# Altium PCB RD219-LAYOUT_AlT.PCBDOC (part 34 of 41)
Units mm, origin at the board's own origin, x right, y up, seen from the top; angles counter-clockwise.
Board outline 209.75 x 159.97 mm, 2 copper layers (TOP, BOTTOM), stack 0 mm thick; 398 components, 199 nets, 1469 pads, 0 vias.
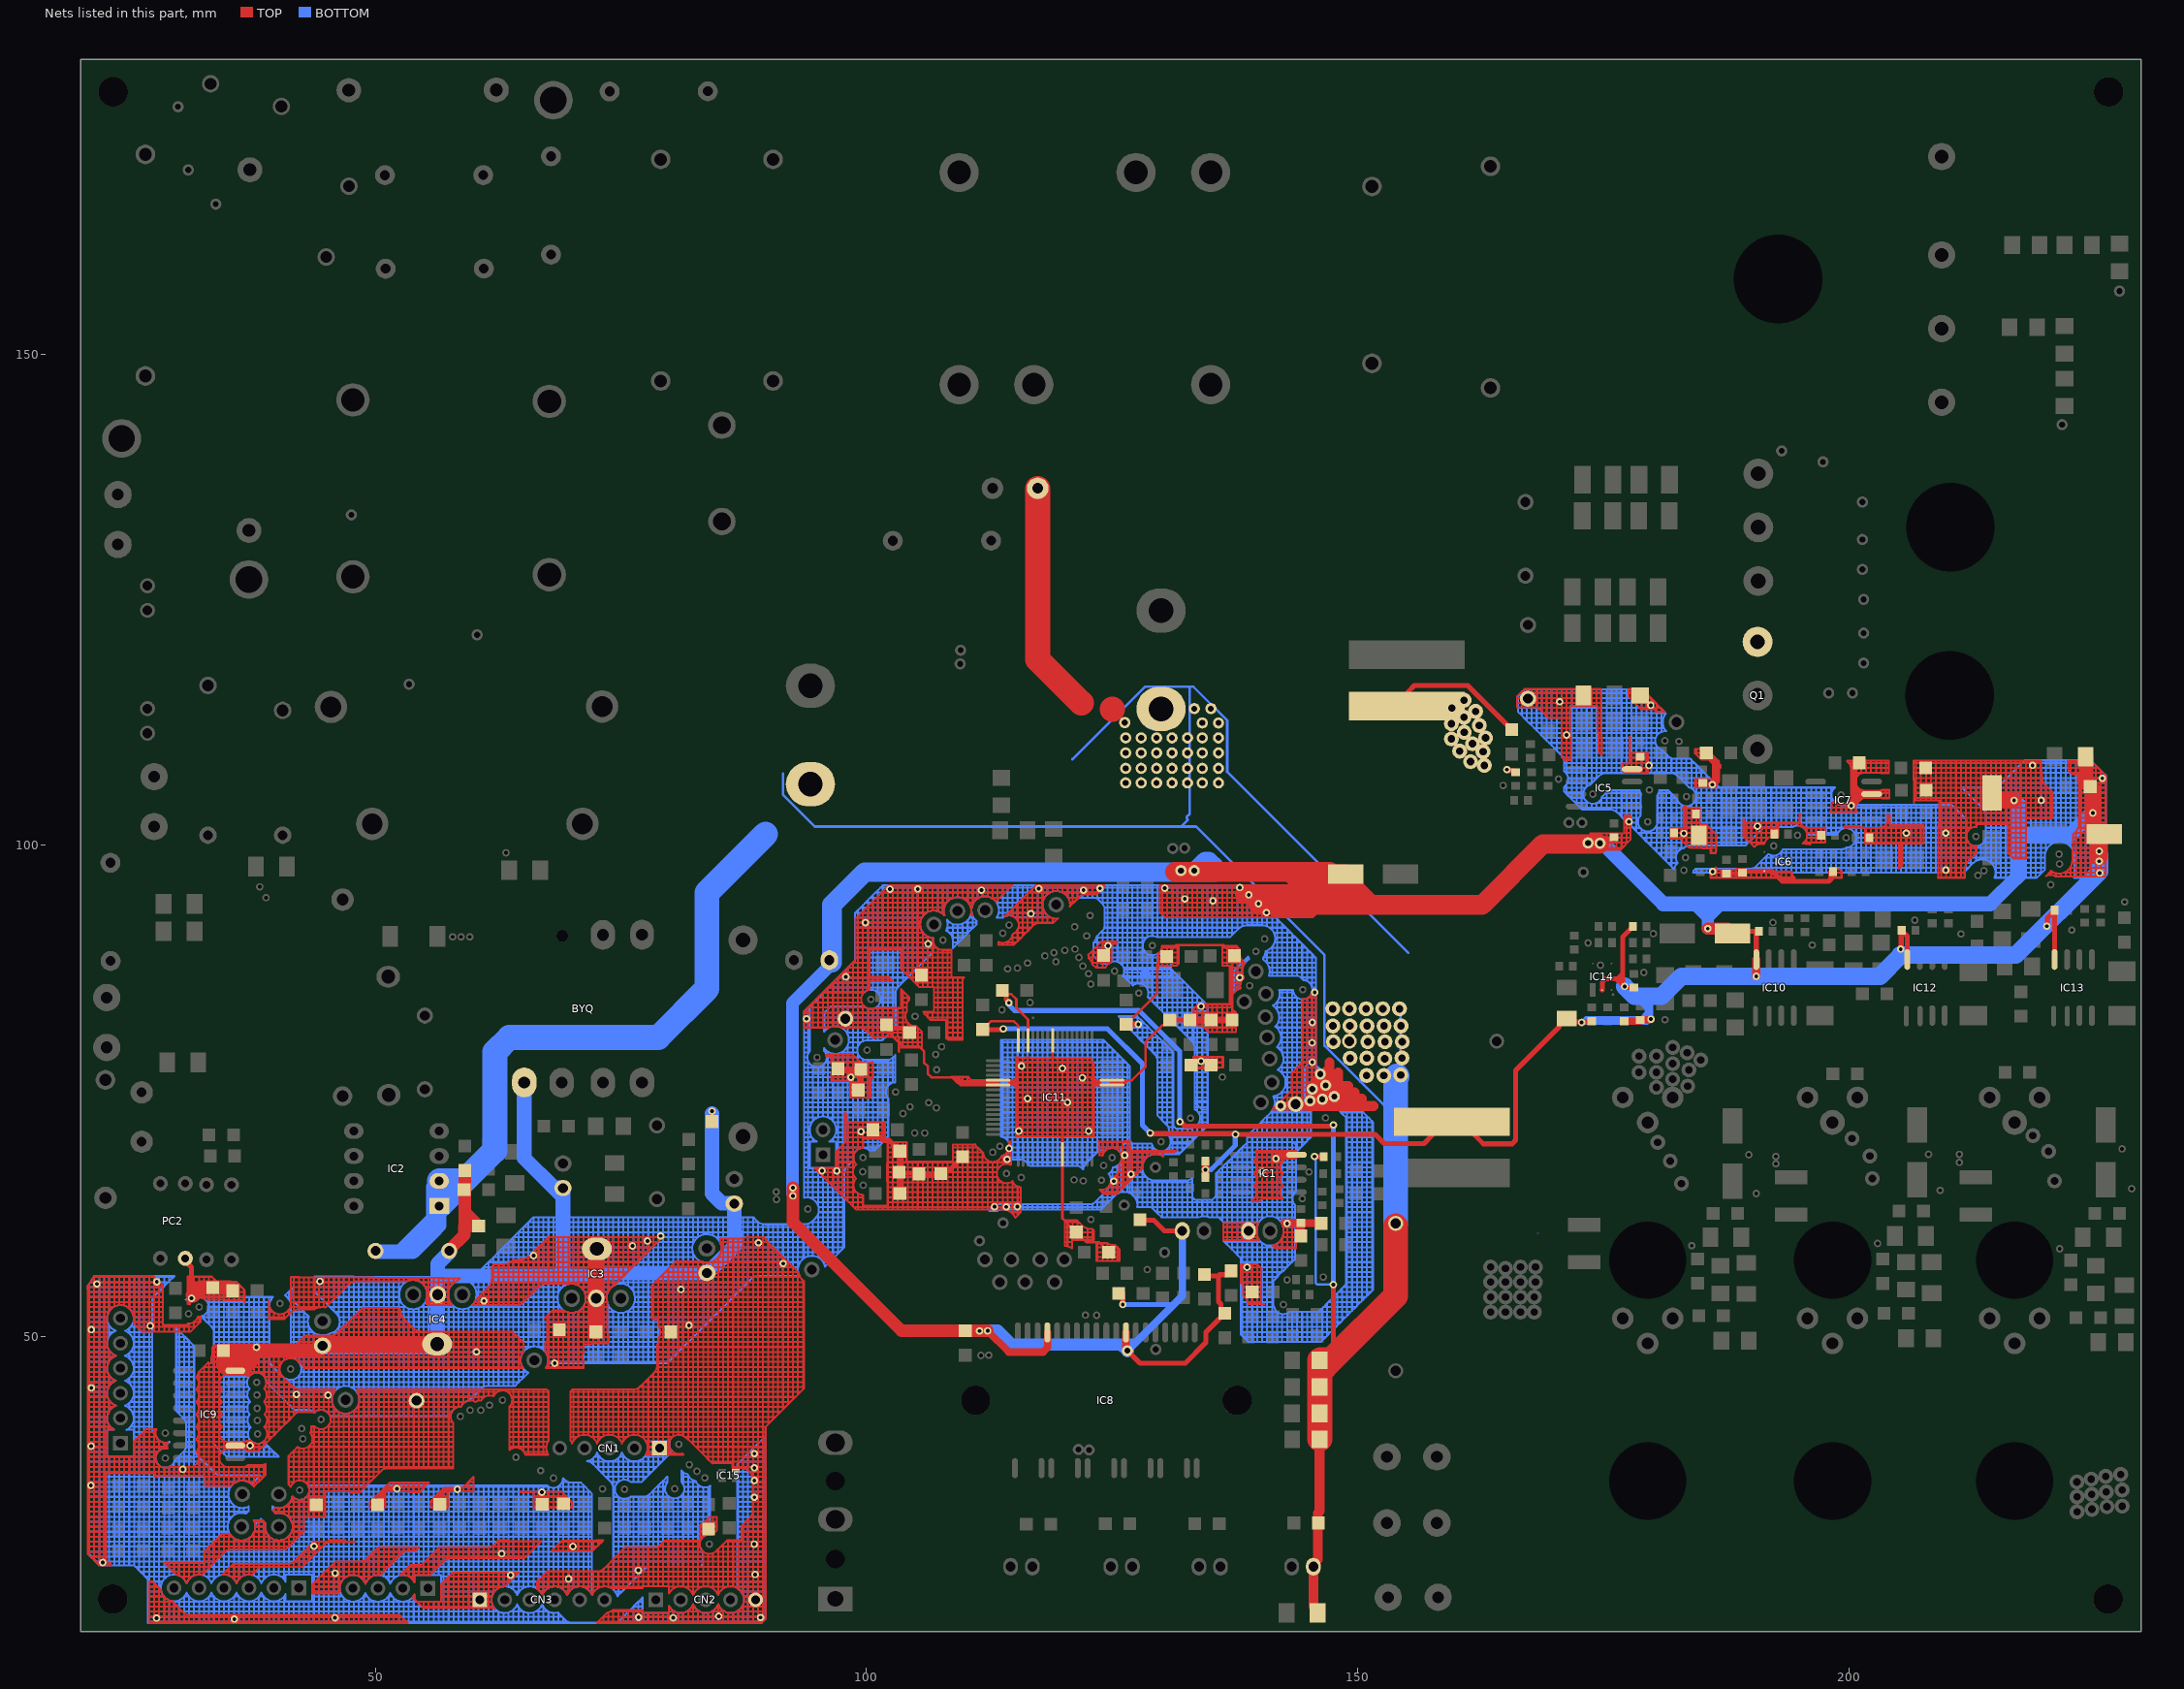
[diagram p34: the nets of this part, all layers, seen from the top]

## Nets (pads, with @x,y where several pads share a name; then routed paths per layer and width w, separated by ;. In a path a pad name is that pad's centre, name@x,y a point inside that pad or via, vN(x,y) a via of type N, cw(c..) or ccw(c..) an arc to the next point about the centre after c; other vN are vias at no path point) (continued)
GND: (continued)
  BOTTOM w0.203: 139.253,63.688 139.761,63.688 ; 139.253,64.196 139.253,64.704 ; 139.253,64.196 139.761,64.196 ; 139.253,64.704 139.253,65.212 ; 139.253,64.704 139.761,64.704 ; 139.253,65.212 139.253,65.72 ; 139.253,65.212 139.761,65.212 ; 139.253,65.72 139.253,66.228 ; 139.253,65.72 139.761,65.72 ; 139.253,66.228 139.253,66.736 ; 139.253,66.228 139.761,66.228 ; 139.253,66.736 139.253,67.244 ; 139.253,66.736 139.761,66.736 ; 139.253,67.244 139.253,67.752 ; 139.253,67.244 139.761,67.244 ; 139.253,67.752 139.253,68.26 ; 139.253,67.752 139.761,67.752 ; 139.253,68.26 139.253,68.768 ; 139.253,68.26 139.761,68.26 ; 139.253,68.768 139.253,69.276 ; 139.253,68.768 139.761,68.768 ; 139.253,69.276 139.253,69.784 ; 139.253,69.276 139.761,69.276 ; 139.253,69.784 139.253,70.292 ; 139.253,69.784 139.761,69.784 ; 139.253,70.292 139.253,70.8 ; 139.253,70.292 139.761,70.292 ; 139.253,70.8 139.253,70.927 ; 139.253,70.8 139.761,70.8 ; 139.253,70.927 139.634,71.308 ; 139.253,91.876 139.761,91.876 ; 139.253,91.876 139.253,92.136 ; 139.253,92.136 139.253,92.644 ; 139.253,92.136 139.761,92.136 ; 139.253,92.644 139.253,93.152 ; 139.253,92.644 139.761,92.644 ; 139.253,93.152 139.761,93.152 ; 139.253,93.152 139.253,93.66 ; 139.253,93.66 139.761,93.66 ; 139.253,93.66 139.253,94.168 ; 139.253,94.168 pad.@139.761,94.168 ; 139.253,94.168 139.253,94.676 ; 139.253,94.676 139.634,94.676 ; 139.253,94.676 pad.@139.253,95.057 ; pad.@139.253,95.057 139.634,94.676 ; 139.634,71.308 139.761,71.308 ; 139.634,71.308 139.761,71.435 ; 139.634,94.676 139.761,94.549 ; 139.72,60.64 139.72,60.917 cw(c141.072,60.917) 139.74,61.148 ; 139.72,60.64 139.72,60.617 ccw(c141.072,60.617) 139.761,60.29 ccw(c141.072,60.617) 139.761,60.288 ; 139.74,61.148 cw(c141.072,60.917) 139.761,61.244 cw(c141.072,60.917) 139.761,61.246 ; 139.761,49.464 140.269,49.464 ; 139.761,49.464 139.761,49.972 ; 139.761,49.972 140.269,49.972 ; 139.761,49.972 139.761,50.48 ; 139.761,50.48 140.269,50.48 ; 139.761,50.48 139.761,50.988 ; 139.761,50.988 140.269,50.988 ; 139.761,50.988 139.761,51.496 ; 139.761,51.496 139.761,52.004 ; 139.761,51.496 140.269,51.496 ; 139.761,52.004 140.269,52.004 ; 139.761,52.004 139.761,52.512 ; 139.761,52.512 139.761,53.02 ; 139.761,52.512 140.269,52.512 ; 139.761,53.02 140.269,53.02 ; 139.761,53.02 139.761,53.528 ; 139.761,53.528 139.761,54.036 ; 139.761,53.528 140.269,53.528 ; 139.761,54.036 139.761,54.544 ; 139.761,54.036 140.269,54.036 ; 139.761,54.544 139.761,55.052 ; 139.761,54.544 140.269,54.544 ; 139.761,55.052 139.761,55.56 ; 139.761,55.052 140.269,55.052 ; 139.761,55.56 139.761,56.068 ; 139.761,55.56 140.269,55.56 ; 139.761,56.068 140.269,56.068 ; 139.761,56.068 139.761,56.576 ; 139.761,56.576 140.269,56.576 ; 139.761,56.576 139.761,57.084 ; 139.761,57.084 139.761,57.592 ; 139.761,57.084 140.269,57.084 ; 139.761,57.592 140.269,57.592 ; 139.761,57.592 139.761,58.1 ; 139.761,58.1 140.269,58.1 ; 139.761,58.1 139.761,58.608 ; 139.761,58.608 139.761,59.116 ; 139.761,58.608 140.269,58.608 ; 139.761,59.116 139.761,59.624 ; 139.761,59.116 140.269,59.116 ; 139.761,59.624 139.761,60.132 ; 139.761,59.624 140.155,59.624 ; 139.761,60.132 139.81,60.132 ; 139.761,60.132 139.761,60.288 ; 139.761,60.288 ccw(c141.072,60.617) 139.81,60.132 ; 139.761,61.246 139.761,61.656 ; 139.761,61.656 139.761,62.164 ; 139.761,62.164 139.761,62.672 ; 139.761,62.164 140.269,62.164 ; 139.761,62.672 139.761,63.18 ; 139.761,62.672 140.269,62.672 ; 139.761,63.18 139.761,63.688 ; 139.761,63.18 140.269,63.18 ; 139.761,63.688 139.761,64.196 ; 139.761,63.688 140.269,63.688 ; 139.761,64.196 139.761,64.704 ; 139.761,64.196 140.269,64.196 ; 139.761,64.704 139.761,65.212 ; 139.761,64.704 140.269,64.704 ; 139.761,65.212 139.761,65.72 ; 139.761,65.212 140.269,65.212 ; 139.761,65.72 139.761,66.228 ; 139.761,65.72 140.269,65.72 ; 139.761,66.228 139.761,66.736 ; 139.761,66.228 140.269,66.228 ; 139.761,66.736 139.761,67.244 ; 139.761,66.736 pad.@140.269,66.736 ; 139.761,67.244 139.761,67.752 ; 139.761,67.244 140.269,67.244 ; 139.761,67.752 139.761,68.26 ; 139.761,67.752 140.269,67.752 ; 139.761,68.26 139.761,68.768 ; 139.761,68.26 140.269,68.26 ; 139.761,68.768 139.761,69.276 ; 139.761,68.768 140.269,68.768 ; 139.761,69.276 139.761,69.784 ; 139.761,69.276 140.269,69.276 ; 139.761,69.784 139.761,70.292 ; 139.761,69.784 140.269,69.784 ; 139.761,70.292 139.761,70.8 ; 139.761,70.292 140.269,70.292 ; 139.761,70.8 139.761,71.308 ; 139.761,70.8 140.269,70.8 ; 139.761,71.308 140.269,71.308 ; 139.761,71.308 139.761,71.435 ; 139.761,71.435 140.142,71.816 ; 139.761,91.876 139.761,92.136 ; 139.761,91.876 140.242,91.876 cw(c140.242,90.524) 140.269,91.875 ; 139.761,92.136 139.761,92.644 ; 139.761,92.136 140.269,92.136 ; 139.761,92.644 139.761,93.152 ; 139.761,92.644 140.269,92.644 ; 139.761,93.152 140.269,93.152 ; 139.761,93.152 139.761,93.66 ; 139.761,93.66 pad.@139.761,94.168 ; 139.761,93.66 140.269,93.66 ; pad.@139.761,94.168 139.761,94.549 ; pad.@139.761,94.168 pad.@140.142,94.168 ; 139.761,94.549 pad.@140.142,94.168 ; 139.81,60.132 ccw(c141.072,60.617) 140.155,59.624 ; 140.142,71.816 140.269,71.816 ; 140.142,71.816 140.269,71.943 ; pad.@140.142,94.168 pad.@140.269,94.041 ; 140.269,49.464 140.269,49.972 ; 140.269,49.464 140.777,49.464 ; 140.269,49.972 140.269,50.48 ; 140.269,49.972 140.777,49.972 ; 140.269,50.48 140.269,50.988 ; 140.269,50.48 140.777,50.48 ; 140.269,50.988 140.269,51.496 ; 140.269,50.988 140.777,50.988 ; 140.269,51.496 140.269,52.004 ; 140.269,51.496 140.777,51.496 ; 140.269,52.004 140.777,52.004 ; 140.269,52.004 140.269,52.512 ; 140.269,52.512 140.269,53.02 ; 140.269,52.512 140.777,52.512 ; 140.269,53.02 140.777,53.02 ; 140.269,53.02 140.269,53.528 ; 140.269,53.528 140.269,54.036 ; 140.269,53.528 140.777,53.528 ; 140.269,54.036 140.269,54.544 ; 140.269,54.036 140.777,54.036 ; 140.269,54.544 140.269,55.052 ; 140.269,54.544 140.777,54.544 ; 140.269,55.052 140.269,55.56 ; 140.269,55.052 140.777,55.052 ; 140.269,55.56 140.269,56.068 ; 140.269,55.56 140.777,55.56 ; 140.269,56.068 140.269,56.576 ; 140.269,56.068 140.777,56.068 ; 140.269,56.576 140.269,57.084 ; 140.269,56.576 140.777,56.576 ; 140.269,57.084 140.269,57.592 ; 140.269,57.084 140.777,57.084 ; 140.269,57.592 140.777,57.592 ; 140.269,57.592 140.269,58.1 ; 140.269,58.1 140.777,58.1 ; 140.269,58.1 140.269,58.608 ; 140.269,58.608 140.269,59.116 ; 140.269,58.608 140.777,58.608 ; 140.269,59.116 140.777,59.116 ; 140.269,62.004 cw(c141.072,60.917) 140.544,62.161 cw(c141.072,60.917) 140.551,62.164 ; 140.269,62.004 140.269,62.164 ; 140.269,62.164 140.269,62.672 ; 140.269,62.164 140.551,62.164 ; 140.269,62.672 140.269,63.18 ; 140.269,62.672 140.777,62.672 ; 140.269,63.18 140.269,63.688 ; 140.269,63.18 140.777,63.18 ; 140.269,63.688 140.269,64.196 ; 140.269,63.688 140.777,63.688 ; 140.269,64.196 140.269,64.704 ; 140.269,64.196 140.777,64.196 ; 140.269,64.704 140.269,65.212 ; 140.269,64.704 140.777,64.704 ; 140.269,65.212 140.269,65.72 ; 140.269,65.212 140.777,65.212 ; 140.269,65.72 140.269,66.228 ; 140.269,65.72 140.777,65.72 ; 140.269,66.228 pad.@140.269,66.736 ; 140.269,66.228 140.777,66.228 ; pad.@140.269,66.736 140.777,66.736 ; pad.@140.269,66.736 140.269,67.244 ; 140.269,67.244 140.269,67.752 ; 140.269,67.244 140.777,67.244 ; 140.269,67.752 140.269,68.26 ; 140.269,67.752 140.777,67.752 ; 140.269,68.26 140.269,68.768 ; 140.269,68.26 140.777,68.26 ; 140.269,68.768 140.269,69.276 ; 140.269,68.768 140.777,68.768 ; 140.269,69.276 140.269,69.784 ; 140.269,69.276 140.777,69.276 ; 140.269,69.784 140.269,70.292 ; 140.269,69.784 140.777,69.784 ; 140.269,70.292 140.269,70.8 ; 140.269,70.292 140.777,70.292 ; 140.269,70.8 140.269,71.308 ; 140.269,70.8 140.777,70.8 ; 140.269,71.308 140.269,71.816 ; 140.269,71.308 140.777,71.308 ; 140.269,71.816 140.777,71.816 ; 140.269,71.816 140.269,71.943 ; 140.269,71.943 140.65,72.324 ; 140.269,91.875 cw(c140.242,90.524) 140.777,91.765 ; 140.269,91.875 140.269,92.136 ; 140.269,92.136 140.269,92.644 ; 140.269,92.136 140.777,92.136 ; 140.269,92.644 140.269,93.152 ; 140.269,92.644 140.777,92.644 ; 140.269,93.152 pad.@140.777,93.152 ; 140.269,93.152 140.269,93.66 ; 140.269,93.66 140.65,93.66 ; 140.269,93.66 pad.@140.269,94.041 ; pad.@140.269,94.041 140.65,93.66 ; 140.363,88.38 cw(c139.634,87.183) 140.718,88.072 ; 140.384,88.58 ccw(c139.634,89.215) 140.608,89.088 ; 140.384,88.58 140.777,88.58 ; 140.551,62.164 cw(c141.072,60.917) 140.768,62.234 cw(c141.072,60.917) 140.777,62.236 ; 140.608,89.088 140.777,89.088 ; 140.65,72.324 140.777,72.324 ; 140.65,72.324 140.777,72.451 ; 140.65,93.66 140.777,93.533 ; 140.718,88.072 cw(c139.634,87.183) 140.777,87.994 ; 140.718,88.072 140.777,88.072 ; 140.777,49.464 140.777,49.972 ; 140.777,49.464 141.285,49.464 ; 140.777,49.972 140.777,50.48 ; 140.777,49.972 141.285,49.972 ; 140.777,50.48 140.777,50.988 ; 140.777,50.48 141.285,50.48 ; 140.777,50.988 140.777,51.496 ; 140.777,50.988 141.285,50.988 ; 140.777,51.496 140.777,52.004 ; 140.777,51.496 141.285,51.496 ; 140.777,52.004 140.777,52.512 ; 140.777,52.004 141.285,52.004 ; 140.777,52.512 140.777,53.02 ; 140.777,52.512 141.285,52.512 ; 140.777,53.02 140.777,53.528 ; 140.777,53.02 141.285,53.02 ; 140.777,53.528 140.777,54.036 ; 140.777,53.528 141.285,53.528 ; 140.777,54.036 140.777,54.544 ; 140.777,54.036 141.285,54.036 ; 140.777,54.544 140.777,55.052 ; 140.777,54.544 141.285,54.544 ; 140.777,55.052 140.777,55.56 ; 140.777,55.052 141.285,55.052 ; 140.777,55.56 140.777,56.068 ; 140.777,55.56 141.285,55.56 ; 140.777,56.068 140.777,56.576 ; 140.777,56.068 141.285,56.068 ; 140.777,56.576 140.777,57.084 ; 140.777,56.576 141.285,56.576 ; 140.777,57.084 140.777,57.592 ; 140.777,57.084 141.285,57.084 ; 140.777,57.592 140.777,58.1 ; 140.777,57.592 141.285,57.592 ; 140.777,58.1 140.777,58.608 ; 140.777,58.1 141.285,58.1 ; 140.777,58.608 140.777,59.116 ; 140.777,58.608 141.285,58.608 ; 140.777,59.116 141.285,59.116 ; 140.777,59.116 140.777,59.298 ; 140.777,59.298 ccw(c141.072,60.617) 141.072,59.265 ccw(c141.072,60.617) 141.283,59.282 ccw(c141.072,60.617) 141.285,59.282 ; 140.777,62.236 cw(c141.072,60.917) 141.283,62.252 cw(c141.072,60.917) 141.285,62.252 ; 140.777,62.236 140.777,62.672 ; 140.777,62.672 140.777,63.18 ; 140.777,62.672 141.285,62.672 ; 140.777,63.18 140.777,63.688 ; 140.777,63.18 141.285,63.18 ; 140.777,63.688 140.777,64.196 ; 140.777,63.688 141.285,63.688 ; 140.777,64.196 140.777,64.704 ; 140.777,64.196 141.285,64.196 ; 140.777,64.704 140.777,65.212 ; 140.777,64.704 141.285,64.704 ; 140.777,65.212 140.777,65.72 ; 140.777,65.212 141.285,65.212 ; 140.777,65.72 140.777,66.228 ; 140.777,65.72 141.285,65.72 ; 140.777,66.228 140.777,66.736 ; 140.777,66.228 141.285,66.228 ; 140.777,66.736 140.777,67.244 ; 140.777,66.736 141.285,66.736 ; 140.777,67.244 140.777,67.752 ; 140.777,67.244 141.285,67.244 ; 140.777,67.752 140.777,68.26 ; 140.777,67.752 141.285,67.752 ; 140.777,68.26 140.777,68.768 ; 140.777,68.26 141.285,68.26 ; 140.777,68.768 141.285,68.768 ; 140.777,68.768 140.777,69.276 ; 140.777,69.276 141.285,69.276 ; 140.777,69.276 140.777,69.784 ; 140.777,69.784 140.777,70.292 ; 140.777,69.784 141.285,69.784 ; 140.777,70.292 141.285,70.292 ; 140.777,70.292 140.777,70.8 ; 140.777,70.8 140.777,71.308 ; 140.777,70.8 141.285,70.8 ; 140.777,71.308 140.777,71.816 ; 140.777,71.308 141.285,71.308 ; 140.777,71.816 140.777,72.324 ; 140.777,71.816 141.285,71.816 ; 140.777,72.324 141.285,72.324 ; 140.777,72.324 140.777,72.451 ; 140.777,72.451 141.158,72.832 ; 140.777,87.994 cw(c139.634,87.183) 140.981,87.569 cw(c139.634,87.183) 140.983,87.564 ; 140.777,87.994 140.777,88.072 ; 140.777,88.072 140.777,88.58 ; 140.777,88.072 141.285,88.072 ; 140.777,88.58 141.285,88.58 ; 140.777,88.58 140.777,89.088 ; 140.777,89.088 141.285,89.088 ; 140.777,89.088 140.777,89.283 ; 140.777,89.283 ccw(c140.242,90.524) 141.225,89.596 ; 140.777,91.765 cw(c140.242,90.524) 141.017,91.631 cw(c140.242,90.524) 141.022,91.628 ; 140.777,91.765 140.777,92.136 ; 140.777,92.136 140.777,92.644 ; 140.777,92.136 141.285,92.136 ; 140.777,92.644 pad.@140.777,93.152 ; 140.777,92.644 141.285,92.644 ; pad.@140.777,93.152 141.158,93.152 ; pad.@140.777,93.152 140.777,93.533 ; 140.777,93.533 141.158,93.152 ; 140.961,86.731 ccw(c139.634,87.183) 141.03,87.056 ; 140.961,86.731 141.285,86.731 ; 140.983,87.564 cw(c139.634,87.183) 141.03,87.061 cw(c139.634,87.183) 141.03,87.056 ; 140.983,87.564 141.285,87.564 ; 141.022,91.628 cw(c140.242,90.524) 141.285,91.384 ; 141.022,91.628 141.285,91.628 ; 141.03,87.056 141.285,87.056 ; 141.158,72.832 141.285,72.832 ; 141.158,72.832 141.285,72.959 ; 141.158,93.152 141.285,93.025 ; 141.225,89.596 ccw(c140.242,90.524) 141.278,89.655 ccw(c140.242,90.524) 141.285,89.664 ; 141.225,89.596 141.285,89.596 ; 141.285,49.464 141.285,49.972 ; 141.285,49.464 141.793,49.464 ; 141.285,49.972 141.285,50.48 ; 141.285,49.972 141.793,49.972 ; 141.285,50.48 141.285,50.988 ; 141.285,50.48 141.793,50.48 ; 141.285,50.988 141.285,51.496 ; 141.285,50.988 141.793,50.988 ; 141.285,51.496 141.285,52.004 ; 141.285,51.496 141.793,51.496 ; 141.285,52.004 141.285,52.512 ; 141.285,52.004 141.793,52.004 ; 141.285,52.512 141.793,52.512 ; 141.285,52.512 141.285,53.02 ; 141.285,53.02 141.285,53.528 ; 141.285,53.02 141.479,53.02 ; 141.285,53.528 141.285,54.036 ; 141.285,53.528 141.412,53.528 ; 141.285,54.036 141.285,54.544 ; 141.285,54.036 141.412,54.036 ; 141.285,54.544 141.285,55.052 ; 141.285,54.544 141.412,54.544 ; 141.285,55.052 141.285,55.56 ; 141.285,55.052 141.412,55.052 ; 141.285,55.56 141.285,56.068 ; 141.285,55.56 141.412,55.56 ; 141.285,56.068 141.793,56.068 ; 141.285,56.068 141.285,56.576 ; 141.285,56.576 141.793,56.576 ; 141.285,56.576 141.285,57.084 ; 141.285,57.084 141.285,57.592 ; 141.285,57.084 141.793,57.084 ; 141.285,57.592 141.793,57.592 ; 141.285,57.592 141.285,58.1 ; 141.285,58.1 141.793,58.1 ; 141.285,58.1 141.285,58.608 ; 141.285,58.608 141.285,59.116 ; 141.285,58.608 141.793,58.608 ; 141.285,59.116 141.793,59.116 ; 141.285,59.116 141.285,59.282 ; 141.285,59.282 ccw(c141.072,60.617) 141.788,59.471 ccw(c141.072,60.617) 141.793,59.474 ; 141.285,62.252 cw(c141.072,60.917) 141.593,62.164 ; 141.285,62.252 141.285,62.672 ; 141.285,62.672 141.285,63.18 ; 141.285,62.672 141.793,62.672 ; 141.285,63.18 141.285,63.688 ; 141.285,63.18 141.793,63.18 ; 141.285,63.688 141.285,64.196 ; 141.285,63.688 141.793,63.688 ; 141.285,64.196 141.285,64.704 ; 141.285,64.196 141.793,64.196 ; 141.285,64.704 141.285,65.212 ; 141.285,64.704 141.793,64.704 ; 141.285,65.212 141.285,65.72 ; 141.285,65.212 141.793,65.212 ; 141.285,65.72 141.285,66.228 ; 141.285,65.72 141.793,65.72 ; 141.285,66.228 141.285,66.736 ; 141.285,66.228 141.793,66.228 ; 141.285,66.736 141.285,67.244 ; 141.285,66.736 141.793,66.736 ; 141.285,67.244 141.285,67.752 ; 141.285,67.244 141.793,67.244 ; 141.285,67.752 141.793,67.752 ; 141.285,67.752 141.285,68.26 ; 141.285,68.26 141.285,68.768 ; 141.285,68.26 pad.@141.793,68.26 ; 141.285,68.768 141.285,69.276 ; 141.285,68.768 141.793,68.768 ; 141.285,69.276 141.285,69.784 ; 141.285,69.276 141.793,69.276 ; 141.285,69.784 141.285,70.292 ; 141.285,69.784 141.793,69.784 ; 141.285,70.292 141.793,70.292 ; 141.285,70.292 141.285,70.8 ; 141.285,70.8 141.285,71.308 ; 141.285,70.8 141.793,70.8 ; 141.285,71.308 141.285,71.816 ; 141.285,71.308 141.793,71.308 ; 141.285,71.816 141.285,72.324 ; 141.285,71.816 141.793,71.816 ; 141.285,72.324 141.285,72.832 ; 141.285,72.324 141.793,72.324 ; 141.285,72.832 141.793,72.832 ; 141.285,72.832 141.285,72.959 ; 141.285,72.959 141.412,73.086 ; 141.285,86.731 141.285,87.056 ; 141.285,86.731 141.793,86.731 ; 141.285,87.056 141.285,87.564 ; 141.285,87.056 141.793,87.056 ; 141.285,87.564 141.285,88.072 ; 141.285,87.564 141.793,87.564 ; 141.285,88.072 141.285,88.58 ; 141.285,88.072 141.793,88.072 ; 141.285,88.58 141.285,89.088 ; 141.285,88.58 141.793,88.58 ; 141.285,89.088 141.285,89.596 ; 141.285,89.088 141.793,89.088 ; 141.285,89.596 141.793,89.596 ; 141.285,89.596 141.285,89.664 ; 141.285,89.664 ccw(c140.242,90.524) 141.527,90.104 ; 141.285,91.384 cw(c140.242,90.524) 141.455,91.12 ; 141.285,91.384 141.285,91.628 ; 141.285,91.628 141.285,92.136 ; 141.285,91.628 141.793,91.628 ; 141.285,92.136 141.285,92.644 ; 141.285,92.136 141.793,92.136 ; 141.285,92.644 141.285,93.025 ; 141.285,92.644 141.666,92.644 ; 141.285,93.025 141.666,92.644 ; 141.318,73.086 ccw(c140.142,73.848) 141.448,73.34 ; 141.318,73.086 141.412,73.086 ; 141.412,53.528 141.412,54.036 ; 141.412,54.036 141.412,54.544 ; 141.412,54.544 141.412,55.052 ; 141.412,55.052 141.412,55.56 ; 141.412,55.56 141.412,55.687 141.793,56.068 ; 141.412,73.086 pad.@141.793,73.086 ; 141.412,73.086 pad.@141.666,73.34 ; 141.448,73.34 ccw(c140.142,73.848) 141.544,73.848 ; 141.448,73.34 pad.@141.666,73.34 ; 141.448,74.356 cw(c140.142,73.848) 141.544,73.848 ; 141.448,74.356 141.793,74.356 ; 141.455,91.12 cw(c140.242,90.524) 141.457,91.117 cw(c140.242,90.524) 141.591,90.612 ; 141.455,91.12 141.793,91.12 ; 141.479,53.02 ccw(c142.428,53.274) 141.793,52.524 ; 141.527,90.104 ccw(c140.242,90.524) 141.594,90.524 ccw(c140.242,90.524) 141.591,90.612 ; 141.527,90.104 141.793,90.104 ; 141.544,73.848 pad.@141.793,73.848 ; 141.591,90.612 141.793,90.612 ; 141.593,62.164 cw(c141.072,60.917) 141.788,62.063 cw(c141.072,60.917) 141.793,62.06 ; 141.593,62.164 141.793,62.164 ; 141.599,83.5 cw(c140.598,82.519) 141.787,83.262 cw(c140.598,82.519) 141.793,83.251 ; 141.599,83.5 141.793,83.5 ; pad.@141.666,73.34 pad.@141.793,73.34 ; pad.@141.666,73.34 pad.@141.793,73.467 ; 141.666,92.644 141.793,92.517 ; 141.734,84.008 ccw(c140.65,84.897) 141.793,84.086 ; 141.734,84.008 141.793,84.008 ; 141.743,81.468 cw(c140.777,80.452) 141.793,81.418 ; 141.743,81.468 141.793,81.468 ; 141.793,49.464 141.793,49.972 ; 141.793,49.464 142.301,49.464 ; 141.793,49.972 141.793,50.48 ; 141.793,49.972 142.301,49.972 ; 141.793,50.48 141.793,50.988 ; 141.793,50.48 142.301,50.48 ; 141.793,50.988 141.793,51.496 ; 141.793,50.988 142.301,50.988 ; 141.793,51.496 141.793,52.004 ; 141.793,51.496 142.301,51.496 ; 141.793,52.004 141.793,52.512 ; 141.793,52.004 142.301,52.004 ; 141.793,52.512 141.793,52.524 ; 141.793,52.512 141.808,52.512 ; 141.793,52.524 ccw(c142.428,53.274) 141.808,52.512 ; 141.793,56.068 141.793,56.576 ; 141.793,56.068 141.901,56.175 ; 141.793,56.576 141.793,57.084 ; 141.793,56.576 142.223,56.576 ; 141.793,57.084 141.793,57.592 ; 141.793,57.084 142.301,57.084 ; 141.793,57.592 142.301,57.592 ; 141.793,57.592 141.793,58.1 ; 141.793,58.1 142.301,58.1 ; 141.793,58.1 141.793,58.608 ; 141.793,58.608 141.793,59.116 ; 141.793,58.608 142.301,58.608 ; 141.793,59.116 142.301,59.116 ; 141.793,59.116 141.793,59.474 ; 141.793,62.06 cw(c141.072,60.917) 142.204,61.656 ; 141.793,62.06 141.793,62.164 ; 141.793,62.164 141.793,62.672 ; 141.793,62.164 142.301,62.164 ; 141.793,62.672 141.793,63.18 ; 141.793,62.672 142.301,62.672 ; 141.793,63.18 141.793,63.688 ; 141.793,63.18 142.301,63.18 ; 141.793,63.688 141.793,64.196 ; 141.793,63.688 142.301,63.688 ; 141.793,64.196 141.793,64.704 ; 141.793,64.196 142.301,64.196 ; 141.793,64.704 141.793,65.212 ; 141.793,64.704 142.301,64.704 ; 141.793,65.212 141.793,65.72 ; 141.793,65.212 142.301,65.212 ; 141.793,65.72 141.793,66.228 ; 141.793,65.72 142.301,65.72 ; 141.793,66.228 141.793,66.736 ; 141.793,66.228 142.301,66.228 ; 141.793,66.736 141.793,67.244 ; 141.793,66.736 142.301,66.736 ; 141.793,67.244 141.793,67.752 ; 141.793,67.244 142.301,67.244 ; 141.793,67.752 142.301,67.752 ; 141.793,67.752 pad.@141.793,68.26 ; pad.@141.793,68.26 141.793,68.768 ; pad.@141.793,68.26 142.301,68.26 ; 141.793,68.768 141.793,69.276 ; 141.793,68.768 142.301,68.768 ; 141.793,69.276 141.793,69.784 ; 141.793,69.276 142.301,69.276 ; 141.793,69.784 141.793,70.292 ; 141.793,69.784 142.301,69.784 ; 141.793,70.292 142.301,70.292 ; 141.793,70.292 141.793,70.8 ; 141.793,70.8 141.793,71.308 ; 141.793,70.8 142.301,70.8 ; 141.793,71.308 141.793,71.816 ; 141.793,71.308 142.301,71.308 ; 141.793,71.816 141.793,72.324 ; 141.793,71.816 142.301,71.816 ; 141.793,72.324 141.793,72.832 ; 141.793,72.324 142.301,72.324 ; 141.793,72.832 pad.@141.793,73.086 ; 141.793,72.832 142.301,72.832 ; pad.@141.793,73.086 pad.@141.793,73.34 ; pad.@141.793,73.086 pad.@142.301,73.086 ; pad.@141.793,73.34 pad.@141.793,73.467 ; pad.@141.793,73.34 pad.@142.301,73.34 ; pad.@141.793,73.467 pad.@141.793,73.848 ; pad.@141.793,73.467 142.047,73.721 pad.@142.301,73.721 ; pad.@141.793,73.848 141.793,74.356 ; pad.@141.793,73.848 pad.@142.301,73.848 ; 141.793,74.356 142.301,74.356 ; 141.793,74.356 141.793,74.585 ; 141.793,74.585 ccw(c141.256,75.88) 142.221,74.864 ; 141.793,81.418 cw(c140.777,80.452) 142.083,80.96 ; 141.793,81.418 141.793,81.468 ; 141.793,81.468 142.301,81.468 ; 141.793,81.468 141.793,81.787 ; 141.793,81.787 ccw(c140.598,82.519) 141.888,81.971 ccw(c140.598,82.519) 141.89,81.976 ; 141.793,83.251 cw(c140.598,82.519) 141.915,82.998 cw(c140.598,82.519) 141.917,82.992 ; 141.793,83.251 141.793,83.5 ; 141.793,83.5 141.793,84.008 ; 141.793,83.5 142.301,83.5 ; 141.793,84.008 142.301,84.008 ; 141.793,84.008 141.793,84.086 ; 141.793,84.086 ccw(c140.65,84.897) 141.798,84.093 ccw(c140.65,84.897) 141.999,84.516 ; 141.793,86.731 141.793,87.056 ; 141.793,86.731 142.301,86.731 ; 141.793,87.056 141.793,87.564 ; 141.793,87.056 142.301,87.056 ; 141.793,87.564 141.793,88.072 ; 141.793,87.564 142.301,87.564 ; 141.793,88.072 141.793,88.58 ; 141.793,88.072 142.301,88.072 ; 141.793,88.58 141.793,89.088 ; 141.793,88.58 142.301,88.58 ; 141.793,89.088 141.793,89.596 ; 141.793,89.088 142.301,89.088 ; 141.793,89.596 141.793,90.104 ; 141.793,89.596 142.301,89.596 ; 141.793,90.104 141.793,90.612 ; 141.793,90.104 142.301,90.104 ; 141.793,90.612 141.793,91.12 ; 141.793,90.612 142.301,90.612 ; 141.793,91.12 141.793,91.628 ; 141.793,91.12 142.301,91.12 ; 141.793,91.628 141.793,92.136 ; 141.793,91.628 142.301,91.628 ; 141.793,92.136 141.793,92.517 ; 141.793,92.136 142.174,92.136 ; 141.793,92.517 142.174,92.136 ; 141.808,52.512 ccw(c142.428,53.274) 141.81,52.51 ccw(c142.428,53.274) 142.301,52.3 ; 141.842,79.436 cw(c141.031,78.293) 142.281,78.928 ; 141.842,79.436 142.301,79.436 ; 141.89,81.976 ccw(c140.598,82.519) 141.999,82.484 ; 141.89,81.976 142.301,81.976 ; 141.901,56.176 cw(c142.801,55.781) 142.223,56.576 ; 141.917,82.992 cw(c140.598,82.519) 142,82.519 cw(c140.598,82.519) 141.999,82.484 ; 141.917,82.992 142.301,82.992 ; 141.999,82.484 142.301,82.484 ; 141.999,84.516 ccw(c140.65,84.897) 142.052,84.897 ccw(c140.65,84.897) 142.046,85.024 ; 141.999,84.516 142.301,84.516 ; 142,85.273 cw(c140.65,84.897) 142.046,85.024 ; 142,85.273 142.301,85.273 ; 142.046,85.024 142.301,85.024 ; 142.083,79.944 ccw(c140.777,80.452) 142.086,79.95 ccw(c140.777,80.452) 142.179,80.452 ; 142.083,79.944 142.301,79.944 ; 142.083,80.96 cw(c140.777,80.452) 142.086,80.954 cw(c140.777,80.452) 142.179,80.452 ; 142.083,80.96 142.301,80.96 ; 142.115,77.404 ccw(c141.031,78.293) 142.301,77.7 ; 142.115,77.404 142.301,77.404 ; 142.174,92.136 142.301,92.009 ; 142.179,80.452 142.301,80.452 ; 142.204,61.656 cw(c141.072,60.917) 142.297,61.488 cw(c141.072,60.917) 142.301,61.479 ; 142.204,61.656 142.301,61.656 ; 142.221,74.864 ccw(c141.256,75.88) 142.301,74.946 ; 142.221,74.864 142.301,74.864 ; 142.221,76.896 cw(c141.256,75.88) 142.301,76.814 ; 142.221,76.896 142.301,76.896 ; 142.223,56.576 cw(c142.801,55.781) 142.301,56.627 ; 142.281,78.928 cw(c141.031,78.293) 142.301,78.886 142.301,78.928 ; 142.281,78.928 142.301,78.928 ; 142.301,49.464 142.301,49.972 ; 142.301,49.464 142.809,49.464 ; 142.301,49.972 142.301,50.48 ; 142.301,49.972 142.809,49.972 ; 142.301,50.48 142.301,50.988 ; 142.301,50.48 142.809,50.48 ; 142.301,50.988 142.301,51.496 ; 142.301,50.988 142.809,50.988 ; 142.301,51.496 142.301,52.004 ; 142.301,51.496 142.809,51.496 ; 142.301,52.004 142.809,52.004 ; 142.301,52.004 142.301,52.3 ; 142.301,52.3 ccw(c142.428,53.274) 142.308,52.299 ccw(c142.428,53.274) 142.809,52.368 ; 142.301,56.627 142.301,57.084 ; 142.301,57.084 142.301,57.592 ; 142.301,57.084 142.809,57.084 ; 142.301,57.592 142.301,58.1 ; 142.301,57.592 142.809,57.592 ; 142.301,58.1 142.301,58.608 ; 142.301,58.1 142.809,58.1 ; 142.301,58.608 142.301,59.116 ; 142.301,58.608 142.809,58.608 ; 142.301,59.116 142.301,59.624 ; 142.301,59.116 142.809,59.116 ; 142.301,59.624 142.809,59.624 ; 142.301,59.624 142.301,60.055 ; 142.301,60.055 ccw(c141.072,60.617) 142.334,60.132 142.809,60.132 ; 142.301,61.479 cw(c141.072,60.917) 142.403,61.152 cw(c141.072,60.917) 142.404,61.148 ; 142.301,61.479 142.301,61.656 ; 142.301,61.656 pad.@142.809,61.656 ; 142.301,61.656 142.301,62.164 ; 142.301,62.164 142.301,62.672 ; 142.301,62.164 142.809,62.164 ; 142.301,62.672 142.301,63.18 ; 142.301,62.672 142.809,62.672 ; 142.301,63.18 142.301,63.688 ; 142.301,63.18 142.809,63.18 ; 142.301,63.688 142.301,64.196 ; 142.301,63.688 142.809,63.688 ; 142.301,64.196 142.301,64.704 ; 142.301,64.196 142.809,64.196 ; 142.301,64.704 142.301,65.212 ; 142.301,64.704 142.809,64.704 ; 142.301,65.212 142.301,65.72 ; 142.301,65.212 142.809,65.212 ; 142.301,65.72 142.301,66.228 ; 142.301,65.72 142.809,65.72 ; 142.301,66.228 142.301,66.736 ; 142.301,66.228 142.809,66.228 ; 142.301,66.736 142.301,67.244 ; 142.301,66.736 142.809,66.736 ; 142.301,67.244 142.301,67.752 ; 142.301,67.244 142.809,67.244 ; 142.301,67.752 142.301,68.26 ; 142.301,67.752 142.809,67.752 ; 142.301,68.26 142.301,68.768 ; 142.301,68.26 142.809,68.26 ; 142.301,68.768 142.809,68.768 ; 142.301,68.768 142.301,69.276 ; 142.301,69.276 142.301,69.784 ; 142.301,69.276 142.809,69.276 ; 142.301,69.784 142.301,70.292 ; 142.301,69.784 142.809,69.784 ; 142.301,70.292 142.809,70.292 ; 142.301,70.292 142.301,70.8 ; 142.301,70.8 142.301,71.308 ; 142.301,70.8 142.809,70.8 ; 142.301,71.308 142.301,71.816 ; 142.301,71.308 142.809,71.308 ; 142.301,71.816 142.301,72.324 ; 142.301,71.816 142.809,71.816 ; 142.301,72.324 142.301,72.832 ; 142.301,72.324 142.809,72.324 ; 142.301,72.832 142.809,72.832 ; 142.301,72.832 pad.@142.301,73.086 ; pad.@142.301,73.086 142.809,73.086 ; pad.@142.301,73.086 pad.@142.301,73.34 ; pad.@142.301,73.34 142.809,73.34 ; pad.@142.301,73.34 pad.@142.301,73.721 ; pad.@142.301,73.721 142.809,73.721 ; pad.@142.301,73.721 pad.@142.301,73.848 ; pad.@142.301,73.848 142.809,73.848 ; pad.@142.301,73.848 142.301,74.356 ; 142.301,74.356 142.809,74.356 ; 142.301,74.356 142.301,74.864 ; 142.301,74.864 142.809,74.864 ; 142.301,74.864 142.301,74.946 ; 142.301,74.946 ccw(c141.256,75.88) 142.562,75.372 ; 142.301,76.814 cw(c141.256,75.88) 142.562,76.388 ; 142.301,76.814 142.301,76.896 ; 142.301,76.896 142.301,77.404 ; 142.301,76.896 142.809,76.896 ; 142.301,77.404 142.809,77.404 ; 142.301,77.404 142.301,77.7 ; 142.301,77.7 ccw(c141.031,78.293) 142.38,77.912 ; 142.301,78.928 142.809,78.928 ; 142.301,78.928 142.301,79.436 ; 142.301,79.436 142.301,79.944 ; 142.301,79.436 142.809,79.436 ; 142.301,79.944 142.301,80.452 ; 142.301,79.944 142.809,79.944 ; 142.301,80.452 142.809,80.452 ; 142.301,80.452 142.301,80.96 ; 142.301,80.96 142.301,81.468 ; 142.301,80.96 142.809,80.96 ; 142.301,81.468 142.301,81.976 ; 142.301,81.468 142.809,81.468 ; 142.301,81.976 142.301,82.484 ; 142.301,81.976 142.809,81.976 ; 142.301,82.484 142.301,82.992 ; 142.301,82.484 142.809,82.484 ; 142.301,82.992 142.301,83.5 ; 142.301,82.992 142.809,82.992 ; 142.301,83.5 142.301,84.008 ; 142.301,83.5 142.809,83.5 ; 142.301,84.008 142.301,84.516 ; 142.301,84.008 142.809,84.008 ; 142.301,84.516 142.301,85.024 ; 142.301,84.516 142.809,84.516 ; 142.301,85.024 142.301,85.273 ; 142.301,85.024 142.809,85.024 ; 142.301,85.273 142.809,85.273 ; 142.301,86.731 142.301,87.056 ; 142.301,86.731 142.809,86.731 ; 142.301,87.056 142.301,87.564 ; 142.301,87.056 142.809,87.056 ; 142.301,87.564 142.301,88.072 ; 142.301,87.564 142.809,87.564 ; 142.301,88.072 142.301,88.58 ; 142.301,88.072 142.809,88.072 ; 142.301,88.58 142.301,89.088 ; 142.301,88.58 142.809,88.58 ; 142.301,89.088 142.301,89.596 ; 142.301,89.088 142.809,89.088 ; 142.301,89.596 142.301,90.104 ; 142.301,89.596 142.809,89.596 ; 142.301,90.104 142.301,90.612 ; 142.301,90.104 142.809,90.104 ; 142.301,90.612 142.301,91.12 ; 142.301,90.612 142.809,90.612 ; 142.301,91.12 142.301,91.628 ; 142.301,91.12 142.809,91.12 ; 142.301,91.628 142.301,92.009 ; 142.301,91.628 142.682,91.628 ; 142.301,92.009 142.682,91.628 ; 142.38,77.912 ccw(c141.031,78.293) 142.433,78.293 ccw(c141.031,78.293) 142.427,78.42 ; 142.38,77.912 142.809,77.912 ; 142.404,61.148 cw(c141.072,60.917) 142.424,60.917 142.424,60.64 ; 142.404,61.148 142.809,61.148 ; 142.424,60.64 142.809,60.64 ; 142.427,78.42 142.809,78.42 ; 142.562,75.372 ccw(c141.256,75.88) 142.658,75.88 ; 142.562,75.372 142.809,75.372 ; 142.562,76.388 cw(c141.256,75.88) 142.658,75.88 ; 142.562,76.388 142.809,76.388 ; 142.658,75.88 142.809,75.88 ; 142.682,91.628 142.809,91.501 ; 142.809,49.464 142.809,49.972 ; 142.809,49.464 143.317,49.464 ; 142.809,49.972 142.809,50.48 ; 142.809,49.972 143.317,49.972 ; 142.809,50.48 142.809,50.988 ; 142.809,50.48 143.317,50.48 ; 142.809,50.988 142.809,51.496 ; 142.809,50.988 143.317,50.988 ; 142.809,51.496 142.809,52.004 ; 142.809,51.496 143.317,51.496 ; 142.809,52.004 143.317,52.004 ; 142.809,52.004 142.809,52.368 ; 142.809,57.084 143.317,57.592 ; 142.809,57.084 142.809,57.592 ; 142.809,57.592 143.317,57.592 ; 142.809,57.592 142.809,58.1 ; 142.809,58.1 143.317,58.1 ; 142.809,58.1 142.809,58.608 ; 142.809,58.608 142.809,59.116 ; 142.809,58.608 143.317,58.608 ; 142.809,59.116 142.809,59.624 ; 142.809,59.116 143.317,59.116 ; 142.809,59.624 142.809,60.132 ; 142.809,59.624 143.317,59.624 ; 142.809,60.132 143.317,60.132 ; 142.809,60.132 142.809,60.64 ; 142.809,60.64 142.809,61.148 ; 142.809,60.64 143.317,60.64 ; 142.809,61.148 143.317,61.148 ; 142.809,61.148 pad.@142.809,61.656 ; pad.@142.809,61.656 142.809,62.164 ; pad.@142.809,61.656 143.317,61.656 ; 142.809,62.164 142.809,62.672 ; 142.809,62.164 143.317,62.164 ; 142.809,62.672 143.317,62.672 ; 142.809,62.672 142.809,63.18 ; 142.809,63.18 143.317,63.18 ; 142.809,63.18 142.809,63.688 ; 142.809,63.688 142.809,64.196 ; 142.809,63.688 143.317,63.688 ; 142.809,64.196 143.317,64.196 ; 142.809,64.196 142.809,64.704 ; 142.809,64.704 143.317,64.704 ; 142.809,64.704 142.809,65.212 ; 142.809,65.212 142.809,65.72 ; 142.809,65.212 143.317,65.212 ; 142.809,65.72 142.809,66.228 ; 142.809,65.72 143.317,65.72 ; 142.809,66.228 142.809,66.736 ; 142.809,66.228 143.317,66.228 ; 142.809,66.736 143.317,66.736 ; 142.809,66.736 142.809,67.244 ; 142.809,67.244 143.317,67.244 ; 142.809,67.244 142.809,67.752 ; 142.809,67.752 142.809,68.26 ; 142.809,67.752 143.317,67.752 ; 142.809,68.26 142.809,68.768 ; 142.809,68.26 143.317,68.26 ; 142.809,68.768 143.317,68.768 ; 142.809,68.768 142.809,69.276 ; 142.809,69.276 143.317,69.276 ; 142.809,69.276 142.809,69.784 ; 142.809,69.784 143.317,69.784 ; 142.809,69.784 142.809,70.292 ; 142.809,70.292 143.317,70.292 ; 142.809,70.292 142.809,70.8 ; 142.809,70.8 142.809,71.308 ; 142.809,70.8 143.317,70.8 ; 142.809,71.308 142.809,71.816 ; 142.809,71.308 143.317,71.308 ; 142.809,71.816 142.809,72.324 ; 142.809,71.816 143.317,71.816 ; 142.809,72.324 142.809,72.832 ; 142.809,72.324 143.317,72.324 ; 142.809,72.832 142.809,73.086 ; 142.809,72.832 143.317,72.832 ; 142.809,73.086 142.809,73.34 ; 142.809,73.086 TP31.1@143.317,73.086 ; 142.809,73.34 TP31.1@143.317,73.34 ; 142.809,73.34 142.809,73.721 ; 142.809,73.721 TP31.1@143.317,73.721 ; 142.809,73.721 142.809,73.848 ; 142.809,73.848 TP31.1@143.317,73.848 ; 142.809,73.848 142.809,74.356 ; 142.809,74.356 TP31.1@143.317,74.356 ; 142.809,74.356 142.809,74.864 ; 142.809,74.864 143.317,74.864 ; 142.809,74.864 142.809,75.372 ; 142.809,75.372 143.317,75.372 ; 142.809,75.372 142.809,75.88 ; 142.809,75.88 143.317,75.88 ; 142.809,75.88 142.809,76.388 ; 142.809,76.388 143.317,76.388 ; 142.809,76.388 142.809,76.896 ; 142.809,76.896 143.317,76.896 ; 142.809,76.896 142.809,77.404 ; 142.809,77.404 143.317,77.404 ; 142.809,77.404 142.809,77.912 ; 142.809,77.912 143.317,77.912 ; 142.809,77.912 142.809,78.42 ; 142.809,78.42 143.317,78.42 ; 142.809,78.42 142.809,78.928 ; 142.809,78.928 142.809,79.436 ; 142.809,78.928 143.317,78.928 ; 142.809,79.436 143.317,79.436 ; 142.809,79.436 142.809,79.944 ; 142.809,79.944 142.809,80.452 ; 142.809,79.944 143.317,79.944 ; 142.809,80.452 143.317,80.452 ; 142.809,80.452 142.809,80.96 ; 142.809,80.96 142.809,81.468 ; 142.809,80.96 143.317,80.96 ; 142.809,81.468 143.317,81.468 ; 142.809,81.468 142.809,81.976 ; 142.809,81.976 142.809,82.484 ; 142.809,81.976 143.317,81.976 ; 142.809,82.484 143.317,82.484 ; 142.809,82.484 142.809,82.992 ; 142.809,82.992 142.809,83.5 ; 142.809,82.992 143.317,82.992 ; 142.809,83.5 142.809,84.008 ; 142.809,83.5 143.317,83.5 ; 142.809,84.008 142.809,84.516 ; 142.809,84.008 143.317,84.008 ; 142.809,84.516 143.317,84.516 ; 142.809,84.516 142.809,85.024 ; 142.809,85.024 143.317,85.024 ; 142.809,85.024 142.809,85.273 ; 142.809,85.273 143.317,85.273 ; 142.809,86.731 142.809,87.056 ; 142.809,86.731 143.317,86.731 ; 142.809,87.056 142.809,87.564 ; 142.809,87.056 143.317,87.056 ; 142.809,87.564 142.809,88.072 ; 142.809,87.564 143.317,87.564 ; 142.809,88.072 142.809,88.58 ; 142.809,88.072 143.317,88.072 ; 142.809,88.58 142.809,89.088 ; 142.809,88.58 143.317,88.58 ; 142.809,89.088 142.809,89.596 ; 142.809,89.088 143.317,89.088 ; 142.809,89.596 142.809,90.104 ; 142.809,89.596 143.317,89.596 ; 142.809,90.104 142.809,90.612 ; 142.809,90.104 143.317,90.104 ; 142.809,90.612 142.809,91.12 ; 142.809,90.612 143.317,90.612 ; 142.809,91.12 142.809,91.501 ; 142.809,91.12 143.19,91.12 ; 142.809,91.501 143.19,91.12 ; 143.19,91.12 143.317,90.993 ; 143.317,49.464 143.317,49.972 ; 143.317,49.464 143.825,49.464 ; 143.317,49.972 143.317,50.48 ; 143.317,49.972 143.825,49.972 ; 143.317,50.48 143.317,50.988 ; 143.317,50.48 143.825,50.48 ; 143.317,50.988 143.317,51.496 ; 143.317,50.988 143.825,50.988 ; 143.317,51.496 143.317,52.004 ; 143.317,51.496 143.825,51.496 ; 143.317,52.004 143.317,52.512 ; 143.317,52.004 143.825,52.004 ; 143.317,52.512 143.825,52.512 ; 143.317,57.592 143.317,58.1 ; 143.317,57.592 143.618,57.893 143.618,58.1 ; 143.317,58.1 143.618,58.1 ; 143.317,58.1 143.317,58.608 ; 143.317,58.608 143.317,59.116 ; 143.317,58.608 143.618,58.608 ; 143.317,59.116 143.317,59.624 ; 143.317,59.116 143.618,59.116 ; 143.317,59.624 143.317,60.132 ; 143.317,59.624 143.618,59.624 ; 143.317,60.132 143.618,60.132 ; 143.317,60.132 143.317,60.64 ; 143.317,60.64 143.317,61.148 ; 143.317,60.64 143.618,60.64 ; 143.317,61.148 143.317,61.656 ; 143.317,61.148 143.618,61.148 ; 143.317,61.656 143.317,62.164 ; 143.317,61.656 143.618,61.656 ; 143.317,62.164 143.317,62.672 ; 143.317,62.164 143.618,62.164 ; 143.317,62.672 143.317,63.18 ; 143.317,62.672 143.618,62.672 ; 143.317,63.18 143.317,63.688 ; 143.317,63.18 143.618,63.18 ; 143.317,63.688 143.317,64.196 ; 143.317,64.196 143.317,64.704 ; 143.317,64.196 143.375,64.196 ; 143.317,64.704 143.317,65.212 ; 143.317,64.704 143.614,64.704 ; 143.317,65.212 143.317,65.72 ; 143.317,65.212 143.698,65.212 ; 143.317,65.72 143.317,66.228 ; 143.317,65.72 143.698,65.72 ; 143.317,66.228 143.317,66.736 ; 143.317,66.228 143.698,66.228 ; 143.317,66.736 143.698,66.736 ; 143.317,66.736 143.317,67.244 ; 143.317,67.244 143.698,67.244 ; 143.317,67.244 143.317,67.752 ; 143.317,67.752 143.317,68.26 ; 143.317,67.752 143.698,67.752 ; 143.317,68.26 143.317,68.768 ; 143.317,68.26 143.698,68.26 ; 143.317,68.768 143.317,69.276 ; 143.317,68.768 143.698,68.768 ; 143.317,69.276 143.317,69.784 ; 143.317,69.276 143.698,69.276 ; 143.317,69.784 143.317,70.292 ; 143.317,69.784 143.444,69.784 ; 143.317,70.292 143.317,70.8 ; 143.317,70.292 143.825,70.292 ; 143.317,70.8 143.317,71.308 ; 143.317,70.8 143.825,70.8 ; 143.317,71.308 143.317,71.816 ; 143.317,71.308 143.825,71.308 ; 143.317,71.816 143.317,72.324 ; 143.317,71.816 143.825,71.816 ; 143.317,72.324 143.317,72.832 ; 143.317,72.324 143.825,72.324 ; 143.317,72.832 TP31.1@143.317,73.086 ; 143.317,72.832 143.825,72.832 ; TP31.1@143.317,73.086 TP31.1@143.317,73.34 ; TP31.1@143.317,73.086 TP31.1@143.825,73.086 ; TP31.1@143.317,73.34 TP31.1@143.317,73.721 ; TP31.1@143.317,73.34 TP31.1@143.825,73.34 ; TP31.1@143.317,73.721 TP31.1@143.317,73.848 ; TP31.1@143.317,73.721 143.676,73.721 TP31.1@143.825,73.721 ; TP31.1@143.317,73.848 TP31.1@143.317,74.356 ; TP31.1@143.317,73.848 TP31.1@143.825,73.848 ; TP31.1@143.317,74.356 143.317,74.864 ; TP31.1@143.317,74.356 TP31.1@143.825,74.356 ; 143.317,74.864 143.825,74.864 ; 143.317,74.864 143.317,75.372 ; 143.317,75.372 143.825,75.372 ; 143.317,75.372 143.317,75.88 ; 143.317,75.88 143.825,75.88 ; 143.317,75.88 143.317,76.388 ; 143.317,76.388 143.825,76.388 ; 143.317,76.388 143.317,76.896 ; 143.317,76.896 143.825,76.896 ; 143.317,76.896 143.317,77.404 ; 143.317,77.404 143.825,77.404 ; 143.317,77.404 143.317,77.912 ; 143.317,77.912 143.825,77.912 ; 143.317,77.912 143.317,78.42 ; 143.317,78.42 143.825,78.42 ; 143.317,78.42 143.317,78.928 ; 143.317,78.928 143.317,79.436 ; 143.317,78.928 143.825,78.928 ; 143.317,79.436 143.317,79.944 ; 143.317,79.436 143.825,79.436 ; 143.317,79.944 143.317,80.452 ; 143.317,79.944 143.825,79.944 ; 143.317,80.452 143.825,80.452 ; 143.317,80.452 143.317,80.96 ; 143.317,80.96 143.317,81.468 ; 143.317,80.96 143.825,80.96 ; 143.317,81.468 143.825,81.468 ; 143.317,81.468 143.317,81.976 ; 143.317,81.976 143.317,82.484 ; 143.317,81.976 143.825,81.976 ; 143.317,82.484 143.317,82.992 ; 143.317,82.484 143.825,82.484 ; 143.317,82.992 143.317,83.5 ; 143.317,82.992 143.825,82.992 ; 143.317,83.5 143.317,84.008 ; 143.317,83.5 143.825,83.5 ; 143.317,84.008 143.317,84.516 ; 143.317,84.008 143.825,84.008 ; 143.317,84.516 143.317,85.024 ; 143.317,84.516 143.825,84.516 ; 143.317,85.024 143.317,85.273 ; 143.317,85.024 143.459,85.024 ; 143.317,86.731 143.317,87.056 ; 143.317,86.731 143.714,86.731 ; 143.317,87.056 143.317,87.564 ; 143.317,87.056 143.825,87.056 ; 143.317,87.564 143.317,88.072 ; 143.317,87.564 143.825,87.564 ; 143.317,88.072 143.825,88.072 ; 143.317,88.072 143.317,88.58 ; 143.317,88.58 143.825,88.58 ; 143.317,88.58 143.317,89.088 ; 143.317,89.088 143.825,89.088 ; 143.317,89.088 143.317,89.596 ; 143.317,89.596 143.317,90.104 ; 143.317,89.596 143.825,89.596 ; 143.317,90.104 143.825,90.104 ; 143.317,90.104 143.317,90.612 ; 143.317,90.612 143.317,90.993 ; 143.317,90.612 143.698,90.612 ; 143.317,90.993 143.698,90.612 ; 143.375,64.196 cw(c144.346,64.049) 143.614,64.704 ; 143.444,69.784 143.825,69.784 ; 143.444,69.784 143.698,69.53 143.698,69.276 ; 143.459,85.024 ccw(c144.396,85.32) 143.825,84.52 ; 143.614,64.704 cw(c144.346,64.049) 143.698,64.787 ; 143.618,58.1 143.618,58.608 ; 143.618,58.608 143.618,59.116 ; 143.618,59.116 143.618,59.624 ; 143.618,59.624 143.618,60.132 ; 143.618,60.132 143.618,60.64 ; 143.618,60.64 143.618,61.148 ; 143.618,61.148 143.618,61.656 ; 143.618,61.656 143.618,62.164 ; 143.618,62.164 143.618,62.672 ; 143.618,62.672 143.618,63.18 ; 143.618,63.18 143.618,63.389 ; 143.698,64.787 143.698,65.212 ; 143.698,65.212 143.698,65.72 ; 143.698,65.72 143.698,66.228 ; 143.698,66.228 143.698,66.736 ; 143.698,66.736 143.698,67.244 ; 143.698,67.244 143.698,67.752 ; 143.698,67.752 143.698,68.26 ; 143.698,68.26 143.698,68.768 ; 143.698,68.768 143.825,68.895 ; 143.698,68.768 143.698,69.276 ; 143.698,69.276 143.825,69.276 ; 143.698,90.612 143.825,90.485 ; 143.714,86.731 cw(c143.714,86.002) 143.825,86.722 ; 143.714,86.731 cw(c143.714,86.002) 143.825,86.722 ; 143.825,49.464 143.825,49.972 ; 143.825,49.464 144.333,49.464 ; 143.825,49.972 143.825,50.48 ; 143.825,49.972 144.333,49.972 ; 143.825,50.48 143.825,50.988 ; 143.825,50.48 144.333,50.48 ; 143.825,50.988 143.825,51.496 ; 143.825,50.988 144.333,50.988 ; 143.825,51.496 143.825,52.004 ; 143.825,51.496 144.333,51.496 ; 143.825,52.004 143.825,52.512 ; 143.825,52.004 144.333,52.004 ; 143.825,52.512 144.333,52.512 ; 143.825,68.895 144.206,69.276 ; 143.825,68.895 143.825,69.276 ; 143.825,69.276 143.825,69.784 ; 143.825,69.276 144.206,69.276 ; 143.825,69.784 144.333,69.784 ; 143.825,69.784 143.825,70.292 ; 143.825,70.292 143.825,70.8 ; 143.825,70.292 144.333,70.292 ; 143.825,70.8 143.825,71.308 ; 143.825,70.8 144.333,70.8 ; 143.825,71.308 143.825,71.816 ; 143.825,71.308 144.333,71.308 ; 143.825,71.816 143.825,72.324 ; 143.825,71.816 144.333,71.816 ; 143.825,72.324 143.825,72.832 ; 143.825,72.324 144.333,72.324 ; 143.825,72.832 TP31.1@143.825,73.086 ; 143.825,72.832 144.333,72.832 ; TP31.1@143.825,73.086 TP31.1@143.825,73.34 ; TP31.1@143.825,73.086 144.333,73.086 ; TP31.1@143.825,73.34 TP31.1@144.333,73.34 ; TP31.1@143.825,73.34 TP31.1@143.825,73.721 ; TP31.1@143.825,73.721 TP31.1@144.333,73.721 ; TP31.1@143.825,73.721 TP31.1@143.825,73.848 ; TP31.1@143.825,73.848 TP31.1@144.333,73.848 ; TP31.1@143.825,73.848 TP31.1@143.825,74.356 ; TP31.1@143.825,74.356 144.333,74.356 ; TP31.1@143.825,74.356 143.825,74.864 ; 143.825,74.864 144.333,74.864 ; 143.825,74.864 143.825,75.372 ; 143.825,75.372 144.333,75.372 ; 143.825,75.372 143.825,75.88 ; 143.825,75.88 144.333,75.88 ; 143.825,75.88 143.825,76.388 ; 143.825,76.388 144.333,76.388 ; 143.825,76.388 143.825,76.896 ; 143.825,76.896 144.333,76.896 ; 143.825,76.896 143.825,77.404 ; 143.825,77.404 144.333,77.404 ; 143.825,77.404 143.825,77.912 ; 143.825,77.912 144.333,77.912 ; 143.825,77.912 143.825,78.42 ; 143.825,78.42 144.333,78.42 ; 143.825,78.42 143.825,78.928 ; 143.825,78.928 143.825,79.436 ; 143.825,78.928 144.333,78.928 ; 143.825,79.436 143.825,79.944 ; 143.825,79.436 144.333,79.436 ; 143.825,79.944 143.825,80.452 ; 143.825,79.944 144.333,79.944 ; 143.825,80.452 144.333,80.452 ; 143.825,80.452 143.825,80.96 ; 143.825,80.96 143.825,81.468 ; 143.825,80.96 144.333,80.96 ; 143.825,81.468 144.333,81.468 ; 143.825,81.468 143.825,81.976 ; 143.825,81.976 143.825,82.484 ; 143.825,81.976 144.333,81.976 ; 143.825,82.484 144.333,82.484 ; 143.825,82.484 143.825,82.992 ; 143.825,82.992 143.825,83.5 ; 143.825,82.992 144.333,82.992 ; 143.825,83.5 143.825,84.008 ; 143.825,83.5 144.333,83.5 ; 143.825,84.008 143.825,84.516 ; 143.825,84.008 144.333,84.008 ; 143.825,84.516 143.825,84.52 ; 143.825,84.516 143.831,84.516 ; 143.825,84.52 ccw(c144.396,85.32) 143.831,84.516 ; 143.825,86.722 cw(c143.714,86.002) 144.196,86.548 ; 143.825,86.722 cw(c143.714,86.002) 144.196,86.548 ; 143.825,86.722 143.825,87.056 ; 143.825,87.056 143.825,87.564 ; 143.825,87.056 144.333,87.056 ; 143.825,87.564 143.825,88.072 ; 143.825,87.564 144.333,87.564 ; 143.825,88.072 143.825,88.58 ; 143.825,88.072 144.333,88.072 ; 143.825,88.58 144.333,88.58 ; 143.825,88.58 143.825,89.088 ; 143.825,89.088 144.333,89.088 ; 143.825,89.088 143.825,89.596 ; 143.825,89.596 143.825,90.104 ; 143.825,89.596 144.333,89.596 ; 143.825,90.104 144.206,90.104 ; 143.825,90.104 143.825,90.485 ; 143.825,90.485 144.206,90.104 ; 143.831,84.516 ccw(c144.396,85.32) 144.333,84.339 ; 144.196,86.548 cw(c143.714,86.002) 144.229,86.517 ; 144.196,86.548 cw(c143.714,86.002) 144.229,86.517 ; 144.196,86.548 144.333,86.548 ; 144.206,69.276 144.333,69.403 ; 144.206,90.104 144.333,89.977 ; 144.333,49.464 144.333,49.972 ; 144.333,49.464 144.841,49.464 ; 144.333,49.972 144.333,50.48 ; 144.333,49.972 144.841,49.972 ; 144.333,50.48 144.333,50.988 ; 144.333,50.48 144.841,50.48 ; 144.333,50.988 144.333,51.496 ; 144.333,50.988 144.841,50.988 ; 144.333,51.496 144.333,52.004 ; 144.333,51.496 144.841,51.496 ; 144.333,52.004 144.333,52.512 ; 144.333,52.004 144.841,52.004 ; 144.333,52.512 144.841,52.512 ; 144.333,69.403 144.333,69.784 ; 144.333,69.403 144.714,69.784 ; 144.333,69.784 144.714,69.784 ; 144.333,69.784 144.333,70.292 ; 144.333,70.292 144.333,70.8 ; 144.333,70.292 144.841,70.292 ; 144.333,70.8 144.333,71.308 ; 144.333,70.8 144.841,70.8 ; 144.333,71.308 144.333,71.816 ; 144.333,71.308 144.841,71.308 ; 144.333,71.816 144.333,72.324 ; 144.333,71.816 144.841,71.816 ; 144.333,72.324 144.333,72.832 ; 144.333,72.324 144.841,72.324 ; 144.333,72.832 144.333,73.086 ; 144.333,72.832 144.841,72.832 ; 144.333,73.086 TP31.1@144.333,73.34 ; 144.333,73.086 144.841,73.086 ; TP31.1@144.333,73.34 144.587,73.34 ; TP31.1@144.333,73.34 TP31.1@144.333,73.721 ; TP31.1@144.333,73.721 144.587,73.721 ; TP31.1@144.333,73.721 TP31.1@144.333,73.848 ; TP31.1@144.333,73.848 144.587,73.848 ; TP31.1@144.333,73.848 144.333,74.356 ; 144.333,74.356 144.587,74.356 ; 144.333,74.356 144.333,74.864 ; 144.333,74.864 144.587,74.864 ; 144.333,74.864 144.333,75.372 ; 144.333,75.372 144.587,75.372 ; 144.333,75.372 144.333,75.88 ; 144.333,75.88 144.587,75.88 ; 144.333,75.88 144.333,76.388 ; 144.333,76.388 144.587,76.388 ; 144.333,76.388 144.333,76.896 ; 144.333,76.896 144.587,76.896 ; 144.333,76.896 144.333,77.404 ; 144.333,77.404 144.587,77.404 ; 144.333,77.404 144.333,77.912 ; 144.333,77.912 144.841,77.912 ; 144.333,77.912 144.333,78.42 ; 144.333,78.42 144.841,78.42 ; 144.333,78.42 144.333,78.928 ; 144.333,78.928 144.333,79.436 ; 144.333,78.928 144.841,78.928 ; 144.333,79.436 144.333,79.944 ; 144.333,79.436 144.841,79.436 ; 144.333,79.944 144.333,80.452 ; 144.333,79.944 144.841,79.944 ; 144.333,80.452 144.841,80.452 ; 144.333,80.452 144.333,80.96 ; 144.333,80.96 144.333,81.468 ; 144.333,80.96 144.841,80.96 ; 144.333,81.468 144.841,81.468 ; 144.333,81.468 144.333,81.976 ; 144.333,81.976 144.333,82.484 ; 144.333,81.976 144.841,81.976 ; 144.333,82.484 144.841,82.484 ; 144.333,82.484 144.333,82.992 ; 144.333,82.992 144.333,83.5 ; 144.333,82.992 144.841,82.992 ; 144.333,83.5 144.333,84.008 ; 144.333,83.5 144.841,83.5 ; 144.333,84.008 144.841,84.008 ; 144.333,84.008 144.333,84.339 ; 144.333,84.339 ccw(c144.396,85.32) 144.841,84.444 ; 144.333,86.548 144.333,87.056 ; 144.333,86.548 144.841,86.548 ; 144.333,87.056 144.333,87.564 ; 144.333,87.056 144.841,87.056 ; 144.333,87.564 144.333,88.072 ; 144.333,87.564 144.841,87.564 ; 144.333,88.072 144.333,88.58 ; 144.333,88.072 144.841,88.072 ; 144.333,88.58 144.841,88.58 ; 144.333,88.58 144.333,89.088 ; 144.333,89.088 144.841,89.088 ; 144.333,89.088 144.333,89.596 ; 144.333,89.596 144.333,89.977 ; 144.333,89.596 144.714,89.596 ; 144.333,89.977 144.714,89.596 ; 144.587,73.34 144.587,73.721 ; 144.587,73.34 144.841,73.34 ; 144.587,73.34 144.714,73.213 144.841,73.213 ; 144.587,73.721 144.587,73.848 ; 144.587,73.721 pad.@144.841,73.721 ; 144.587,73.848 pad.@144.841,73.848 ; 144.587,73.848 144.587,74.356 ; 144.587,74.356 144.587,74.864 ; 144.587,74.356 pad.@144.841,74.356 ; 144.587,74.864 144.841,74.864 ; 144.587,74.864 144.587,75.372 ; 144.587,75.372 pad.@144.841,75.372 ; 144.587,75.372 144.587,75.88 ; 144.587,75.88 144.587,76.388 ; 144.587,75.88 144.841,75.88 ; 144.587,76.388 144.587,76.896 ; 144.587,76.388 144.841,76.388 ; 144.587,76.896 144.587,77.404 ; 144.587,76.896 144.841,76.896 ; 144.587,77.404 144.841,77.404 ; 144.587,77.404 144.841,77.658 ; 144.714,69.784 144.841,69.911 ; 144.714,89.596 144.841,89.469 ; 144.841,49.464 144.841,49.972 ; 144.841,49.464 145.349,49.464 ; 144.841,49.972 144.841,50.48 ; 144.841,49.972 145.349,49.972 ; 144.841,50.48 144.841,50.988 ; 144.841,50.48 145.349,50.48 ; 144.841,50.988 144.841,51.496 ; 144.841,50.988 145.349,50.988 ; 144.841,51.496 144.841,52.004 ; 144.841,51.496 145.349,51.496 ; 144.841,52.004 144.841,52.512 ; 144.841,52.004 145.349,52.004 ; 144.841,52.512 145.349,52.512 ; 144.841,69.911 144.841,70.292 ; 144.841,69.911 145.222,70.292 ; 144.841,70.292 144.841,70.8 ; 144.841,70.292 145.222,70.292 ; 144.841,70.8 144.841,71.308 ; 144.841,70.8 145.222,70.8 ; 144.841,71.308 145.222,71.308 ; 144.841,71.308 144.841,71.816 ; 144.841,71.816 145.222,71.816 ; 144.841,71.816 144.841,72.324 ; 144.841,72.324 144.841,72.832 ; 144.841,72.324 145.222,72.324 ; 144.841,72.832 144.841,73.086 ; 144.841,72.832 145.222,72.832 ; 144.841,73.086 144.841,73.213 ; 144.841,73.086 144.848,73.086 144.975,73.213 ; 144.841,73.213 144.975,73.213 ; 144.841,73.213 144.841,73.34 ; 144.841,73.34 145.102,73.34 ; 144.841,73.34 pad.@144.841,73.721 ; pad.@144.841,73.721 144.851,73.721 145.164,73.402 ; pad.@144.841,73.721 pad.@144.841,73.848 ; pad.@144.841,73.848 pad.@144.841,74.356 ; pad.@144.841,73.848 pad.@145.349,73.848 ; pad.@144.841,74.356 144.841,74.864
